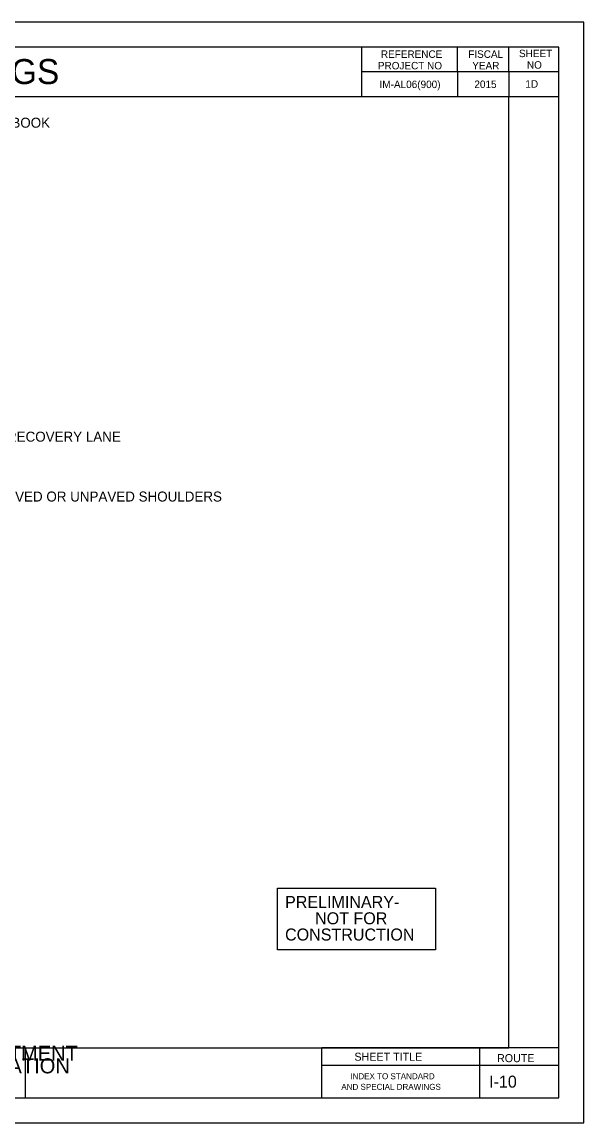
# Model space of a CAD drawing. Extents: x -12822 to 16384, y -6351 to 1913.
# Drawn here: x 289 to 850, y -3350 to -2250 of the extents above; entities that cross this region are included whole.
import ezdxf

# ---------------------------------------------------------------- set-up
doc = ezdxf.new("R2010")
doc.units = 0
for name, color, linetype in [('1', 7, 'Continuous'), ('ANNO-SHT', 7, 'Continuous'), ('ANNO-TXT', 7, 'Continuous'), ('Level 10', 7, 'Continuous'), ('Level 6', 7, 'Continuous'), ('Level 62', 7, 'Continuous'), ('SHT-BDR', 7, 'Continuous'), ('SHT-BNDRY', 7, 'Continuous')]:
    doc.layers.add(name, color=color, linetype=linetype)

msp = doc.modelspace()

# ---------------------------------------------------------------- linework, layer by layer
at = {"layer": '1'}
msp.add_lwpolyline([(544, -3115.2), (701.6, -3115.2), (701.6, -3177), (544, -3177)], close=True, dxfattribs=at)
at = {"layer": 'ANNO-TXT'}
for p, q in [((588.3, -3292.2), (745.9, -3292.2)), ((745.9, -3292.2), (825, -3292.2))]:
    msp.add_line(p, q, dxfattribs=at)
at = {"layer": 'Level 6'}
for p, q in [((627.7, -2274.9), (627.7, -2324.8)), ((723.5, -2299.9), (723.5, -2274.9)), ((775, -2299.2), (775, -2274.9)), ((825, -2299.6), (627.7, -2299.6)), ((723.5, -2299.9), (723.5, -2324.8)), ((775, -2299.2), (775, -2324.8)), ((825, -2324.8), (633.7, -2324.8)), ((825, -3274.8), (588.3, -3274.8))]:
    msp.add_line(p, q, dxfattribs=at)
at = {"layer": 'Level 62'}
msp.add_lwpolyline([(-850, -3349.9), (850, -3349.9), (850, -2249.9), (-850, -2249.9)], close=True, dxfattribs=at)
at = {"layer": 'SHT-BDR'}
msp.add_lwpolyline([(-725, -3274.8), (775, -3274.8), (775, -2324.8), (-725, -2324.8)], close=True, dxfattribs=at)
at = {"layer": 'SHT-BNDRY'}
for p, q in [((292.3, -3324.9), (292.3, -3274.8)), ((588.3, -3324.9), (588.3, -3274.8)), ((745.9, -3324.9), (745.9, -3274.8))]:
    msp.add_line(p, q, dxfattribs=at)
msp.add_lwpolyline([(-787.5, -3324.9), (825, -3324.9), (825, -2274.9), (-787.5, -2274.9)], close=True, dxfattribs=at)

# ---------------------------------------------------------------- texts
at = {"layer": '1'}
for s, p in [('PRELIMINARY-', (551.4, -3135.1)), ('NOT FOR', (581.4, -3151.4)), ('CONSTRUCTION', (551.4, -3167.6))]:
    msp.add_text(s, height=12, dxfattribs=at).set_placement(p)
at = {"layer": 'ANNO-SHT'}
for s, height, p in [('INDEX TO STANDARD AND SPECIAL DRAWINGS', 24.997, (-448.6, -2311.9)), ('IM-AL06(900)', 7.449, (645.8, -2315.9)), ('2015', 7.45, (740.5, -2315.8)), (' 1D ', 7.45, (788.7, -2315.5)), ('AND SPECIAL DRAWINGS', 6, (607.6, -3316.8)), ('INDEX TO STANDARD', 6, (616.6, -3306.2)), ('  I-10  ', 12, (746.3, -3314.6))]:
    msp.add_text(s, height=height, dxfattribs=at).set_placement(p)
at = {"layer": 'ANNO-TXT'}
for s, p in [('ALABAMA DEPARTMENT', (106, -3287.8)), ('OF TRANSPORTATION', (118, -3300.3))]:
    msp.add_text(s, height=15, rotation=360, dxfattribs=at).set_placement(p)
for s, p in [('SHEET TITLE', (620.7, -3287.7)), ('ROUTE', (763.1, -3289.1))]:
    msp.add_text(s, height=8, dxfattribs=at).set_placement(p)
at = {"layer": 'Level 10'}
for s, p in [('ALABAMA DEPARTMENT OF TRANSPORTATION SPECIAL AND STANDARD HIGHWAY DRAWINGS BOOK', (-348.3, -2355.5)), ('DETAILS SHOWING NOSE GORE REQUIRED ADJACENT TO PARALLEL RECOVERY LANE AND REQUIRED ADJACENT TO RECOVERY LANE', (-502.1, -2669.2)), ('DETAILS OF TRAFFIC STRIPING ACCEL AND DECEL LANES AND RAMPS FOR 4 LANE RURAL HIGHWAYS WITH EITHER PAVED OR UNPAVED SHOULDERS', (-502.1, -2729))]:
    msp.add_text(s, height=10, dxfattribs=at).set_placement(p)
at = {"layer": 'Level 6'}
for s, p in [('REFERENCE', (647.1, -2285.7)), ('FISCAL', (734.4, -2285.7)), ('SHEET', (785.1, -2285)), ('PROJECT NO', (644.1, -2297.2)), ('YEAR', (738.4, -2297.2)), ('NO', (793, -2296.5))]:
    msp.add_text(s, height=7.44, dxfattribs=at).set_placement(p)

doc.saveas('drawing.dxf')
